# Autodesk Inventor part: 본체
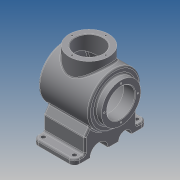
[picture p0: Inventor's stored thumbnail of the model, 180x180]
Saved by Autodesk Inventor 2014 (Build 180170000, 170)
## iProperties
Created: 2018-08
Part Number: 본체
Material: Generic
Document SubType Name: Modeling
Designer: kb542
Density: 1 g/cm^3
Appearance: Default
Mass: 695.959 g
Surface Area: 1087.45 cm^2
Volume: 695.959 cm^3
Author: kb542
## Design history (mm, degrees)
sketch "스케치1"
  geometry: L1 (-48, 50)-(48.671, 50); L2 (-48, 50)-(-48, 38); L3 (-48, 38)-(-60, 38); L4 (-60, 38)-(-60, 27); L5 (-60, 27)-(-38, 27); L6 (-38, 27)-(-38, 40); L7 (-38, 40)-(42.163, 40); L8 (-60, 0)-(60, 0); A1 r 116 centre (-56, 0) between (60, 0) and (48.671, 50); A2 r 106 centre (-56, 0) between (50, 0) and (42.163, 40); 2 further points
  constraints: 16 end point, 4 parallel, 4 point on circle, 2 centre point, 2 horizontal, 2 perpendicular, 2 point on line, 1 coincident, 1 midpoint, 1 vertical alignment
  dimensions: "d0" = 120 distance of L8.end L8.start; "d4" = 10 radial gap between concentric circles of A1 A2; "d5" = 80 diameter of L7 L8; "d6" = 100 diameter of L1 L8; "d7" = 76 diameter of L3 L8; "d8" = 54 diameter of L5 L8; "d9" = 12 distance of L2.end L3.end; "d10" = 22 distance of L4.end L5.end; "d12" = 116 radius of A1
revolve "회전1" sketch "스케치1" stored, may be unused: angle "d13" = 90 deg
node "작업 평면1"
sketch "스케치2"
  geometry: L1 (40, -70)-(-40, -70); L2 (-40, -70)-(-40, 70); L3 (-40, 70)-(40, 70); L4 (40, 70)-(40, -70); L5 (48, 50)-(48, -50) reference; 2 further points
  constraints: 8 end point, 2 parallel, 1 horizontal, 1 horizontal alignment, 1 midpoint, 1 perpendicular
  dimensions: "d15" = 80 distance of L1.start L1.end; "d16" = 140 distance of L1.end L2.end; "d17" = 8 distance between parallel lines of L4 L5
extrude "돌출1" join sketch "스케치2" distance "d18" = 10; taper "d19" = 0 deg
sketch "스케치3"
  geometry: L1 (70, -72)-(-70, -72) reference; L2 (-50, -72)-(-50, -43.437); L3 (50, -72)-(50, -43.437); L4 (70, -82)-(70, -72) reference; L5 (-70, -82)-(-70, -72) reference; L6 (70, -72)-(40.304, -29.59); L7 (-70, -72)-(-40.304, -29.59); L8 (-50, -72)-(50, -72); A1 r 50 centre (0, 0) between (40.304, -29.59) and (-40.304, -29.59) reference; 1 further point
  constraints: 10 end point, 4 point on line, 2 point on circle, 1 collinear, 1 parallel, 1 perpendicular
  dimensions: "d20" = 20 distance between parallel lines of L4 L3; "d21" = 20 distance between parallel lines of L2 L5; "d24" = 35 deg angle of L6 L4; "d26" = 35 deg angle of L7 L5
extrude "돌출2" join sketch "스케치3" stored distance "d27" = 80; taper "d28" = 0 deg
sketch "스케치4"
  geometry: L1 (0, 0)-(0, 140) reference; A1 r 50 centre (82, 70) between (52.41, 110.304) and (52.41, 29.696) reference; A2 r 12.5 centre (0, 97.5) between (0, 85) and (0, 110); A3 r 17.5 centre (0, 47.5) between (0, 30) and (0, 65)
  constraints: 6 point on line, 4 point on circle, 2 centre point
  dimensions: "d31" = 12.5 radius of A2; "d32" = 17.5 radius of A3; "d33" = 27.5 vertical distance of A2.centre A1.centre; "d34" = 22.5 vertical distance of A3.centre A1.centre
extrude "돌출3" cut sketch "스케치4" stored distance "d35" = 80; taper "d36" = 0 deg
fillet "모깎기1" dims "d37" = 10
hole "구멍1" diameter "d40" = 8; stored, may be unused: countersink angle "d44" = 90 deg, drill point angle "d46" = 118 deg; dims "d38" = 10, "d39" = 10, "d41" = 6, "d42" = 4, "d43" = 2, "d45" = 8
hole "구멍2" diameter "d49" = 8; stored, may be unused: countersink angle "d53" = 90 deg, drill point angle "d55" = 118 deg; dims "d47" = 10, "d48" = 10, "d50" = 6, "d51" = 4, "d52" = 2, "d54" = 8
hole "구멍3" diameter "d58" = 8; stored, may be unused: countersink angle "d62" = 90 deg, drill point angle "d64" = 118 deg; dims "d56" = 10, "d57" = 10, "d59" = 6, "d60" = 4, "d61" = 2, "d63" = 8
hole "구멍4" diameter "d67" = 8; stored, may be unused: countersink angle "d71" = 90 deg, drill point angle "d73" = 118 deg; dims "d65" = 10, "d66" = 10, "d68" = 6, "d69" = 4, "d70" = 2, "d72" = 8
node "작업 평면2"
sketch "스케치5"
  geometry: L1 (48, 50)-(48, -50) reference; C1 r 38 at (-2, 0); 1 further point
  constraints: 1 centre point, 1 horizontal alignment
  dimensions: "d75" = 76 diameter of C1; "d76" = 50 distance from line of C1.centre L1
extrude "돌출4" join sketch "스케치5" stored distance "d77" = 80; taper "d78" = 0 deg
hole "구멍5" diameter "d81" = 54; stored, may be unused: countersink angle "d85" = 90 deg, drill point angle "d87" = 118 deg; dims "d79" = 10, "d80" = 10, "d82" = 6, "d83" = 4, "d84" = 2, "d86" = 8
sketch "스케치6"
  geometry: C1 r 38 at (0, 0) reference; 1 further point
  constraints: 1 horizontal alignment
  dimensions: "d88" = 32.5 distance of C1.centre point (-32.5, 0)
hole "구멍6" sketch "스케치6" at (-32.5, 0) diameter "d89" = 3.242; stored, may be unused: countersink angle "d93" = 90 deg, drill point angle "d95" = 118 deg; dims "d90" = 8, "d91" = 4, "d92" = 2, "d94" = 10
sketch "스케치7"
  geometry: C1 r 27 at (0, 0) reference; 2 further points
  constraints: 1 vertical alignment
  dimensions: "d99" = 32.5 distance of C1.centre point (0, -32.5)
hole "구멍7" sketch "스케치7" at (0, -32.5) diameter "d100" = 3.242; stored, may be unused: countersink angle "d104" = 90 deg, drill point angle "d106" = 118 deg; dims "d101" = 8, "d102" = 4, "d103" = 2, "d105" = 10
chamfer "모따기1" distance "d110" = 1; stored, may be unused: second distance "d111" = 2, angle "d112" = 45 deg
fillet "모깎기2" dims "d113" = 3
fillet "모깎기3" dims "d114" = 3
fillet "모깎기4" dims "d115" = 3
fillet "모깎기5" dims "d116" = 3
fillet "모깎기6" dims "d117" = 3
node "작업 평면3"
sketch "스케치8"
  geometry: C1 r 32.5 at (0, 0); 1 further point
  constraints: 1 centre point, 1 coincident, 1 other
  dimensions: "d118" = 65 diameter of C1
feature "엠보싱1" sketch "스케치8" dims "d119" = 0.5, "d120" = 0
node "솔리드1"
pattern_circular "원형 패턴1" dims angle "d97" = 360 deg
pattern_circular "원형 패턴2" dims angle "d108" = 360 deg
other parameters: "d14" = -82, "d74" = -147
